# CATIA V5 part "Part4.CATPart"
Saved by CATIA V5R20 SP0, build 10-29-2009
Part number: Part4
Bounding box of the stored display mesh (mm): x 0 to 2.5, y -3.991 to 30.991, z -4 to 4
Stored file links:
  E:\Ehsan\Catia\Tamrin\Digital Mockup\4\Part4.CATPart
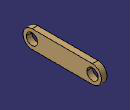
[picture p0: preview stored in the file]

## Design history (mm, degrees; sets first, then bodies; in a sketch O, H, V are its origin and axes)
Body1 (main body)
  DatumCurve1
  Sketch1 on yz-plane, origin (0, 0, 0), H (0, 1, 0), V (0, 0, 1)
    construction line L1 (0, 0) -> (27, 0)
    line L2 (0, 4) -> (27, 4)
    line L3 (27, -4) -> (0, -4)
    arc A1 centre (27, 0) radius 4 from (27, 4) to (27, -4) cw
    arc A2 centre (0, 0) radius 4 from (0, -4) to (0, 4) cw
    projected circle E1 centre (0, 0) radius 2.5 from edge of DatumCurve1
    circle A3 centre (27, 0) radius 2.5
    length L1 = 27
    distance L1 L2 = 4
    radius A3 = 2.5
    horizontal: L1 H
    tangency: A1 L2, A2 L2, A1 L3, A2 L3
  Pad1: profile Sketch1, direction (1, 0, 0), length 2.5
